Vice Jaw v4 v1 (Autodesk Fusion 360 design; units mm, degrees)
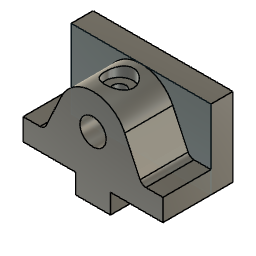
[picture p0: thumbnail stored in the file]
sketch "Sketch1" plane through (0, 0, 0) normal (0, 0, 1) x axis (1, 0, 0)
  line L1 (-32, 5) -> (32, 5)
  line L2 (-32, -5) -> (-32, 5)
  line L3 (32, -5) -> (-32, -5)
  line L4 (32, 5) -> (32, -5)
  line L5 (-32, -5) -> (32, 5)
  line L6 (32, -5) -> (-32, 5)
  point P6 (0, 0)
  point P1 (0, 0)
  point P4 (-32, -5)
  point P5 (32, -5)
  point P3 (-32, 5)
  horizontal L1
  perpendicular L1 L2
  parallel L1 L3
  parallel L2 L4
  coincident L5 P6
  coincident L6 P6
  coincident P1 P6
  dimension "d1" distance P4 P5 = 64
  dimension "d2" distance P3 P4 = 10
extrude "Extrude1" new body sketch "Sketch1" profile of L1 L2 L3 L4 along normal blind 36
sketch "Sketch2" plane through (0, -5, 0) normal (0, -1, 0) x axis (1, 0, 0)
sketch "Sketch3" plane through (0, -5, 0) normal (0, -1, 0) x axis (1, 0, 0)
  line L1 (32, 0) -> (-32, 0)
  line L2 (32, 36) -> (32, 0)
  line L3 (-32, 36) -> (32, 36)
  line L4 (-32, 0) -> (-32, 36)
sketch "Sketch4" plane through (0, -5, 0) normal (0, -1, 0) x axis (1, 0, 0)
  line L1 (-32, 10) -> (-32, 0)
  line L2 (-24.2283, 10) -> (-32, 10)
  line L3 (21.5094, 11.7321) -> (14.5009, 26.7619)
  line L4 (-32, 36) -> (32, 36)
  line L5 (0, 41.3569) -> (0, 0)
  line L6 (32, 10) -> (32, 0)
  line L7 (24.2283, 10) -> (32, 10)
  line L8 (-8, 0) -> (-32, 0)
  line L9 (-8, -9) -> (-8, 0)
  line L10 (8, -9) -> (-8, -9)
  line L11 (8, 0) -> (8, -9)
  line L12 (32, 0) -> (8, 0)
  line L13 (-14.5009, 26.7619) -> (-21.5094, 11.7321)
  arc A1 centre (-24.2283, 13) radius 3 clockwise from (-21.5094, 11.7321) to (-24.2283, 10)
  arc A2 centre (24.2283, 13) radius 3 clockwise from (24.2283, 10) to (21.5094, 11.7321)
  arc A3 centre (0, 20) radius 16 clockwise from (-14.5009, 26.7619) to (14.5009, 26.7619)
  point P2 (-32, 0)
  point P8 (-32, 0)
  point P1 (0, 0)
  point P11 (0, 0)
  point P13 (32, 0)
  point P18 (32, 0)
  point P23 (0, 20)
  point P14 (32, 10)
  vertical L1
  perpendicular L1 L2
  tangent L2 A1
  coincident P2 P8
  tangent A1 L13
  coincident P1 P11
  perpendicular L4 L5
  parallel L5 L6
  perpendicular L5 L7
  tangent L7 A2
  tangent L3 A2
  coincident P13 P18
  perpendicular L1 L8
  perpendicular L8 L9
  perpendicular L1 L10
  perpendicular L8 L11
  perpendicular L6 L12
  symmetric L5 L9 L11
  symmetric L3 L5 L13
  symmetric L2 L5 L7
  symmetric A1 L5 A2
  coincident L5 P23
  tangent L4 A3
  tangent L3 A3
  tangent L13 A3
  dimension "d12" diameter A3 = 32
  dimension "d13" radius A2 = 3
  dimension "d14" distance P13 P14 = 10
  dimension "d15" angle L5 L13 = 25
  dimension "d16" distance L8 L10 = 9
  dimension "d17" distance P1 L9 = 8
extrude "Extrude2" add sketch "Sketch4" profile of L1 L2 A1 L13 L3 L6 L7 A2 L8 L9 L10 L11 L12 A3 along normal blind 22
sketch "Sketch5" plane through (0, -27, 0) normal (0, -1, 0) x axis (1, 0, 0)
  line L1 (14.5009, 26.7619) -> (21.5094, 11.7321)
  line L2 (-21.5094, 11.7321) -> (-14.5009, 26.7619)
  line L3 (-32, 10) -> (-24.2283, 10)
  line L4 (-32, 0) -> (-32, 10)
  line L5 (-8, 0) -> (-32, 0)
  line L6 (-8, -9) -> (-8, 0)
  line L7 (8, -9) -> (-8, -9)
  line L8 (8, 0) -> (8, -9)
  line L9 (32, 0) -> (8, 0)
  line L10 (32, 10) -> (32, 0)
  line L11 (24.2283, 10) -> (32, 10)
  arc A1 centre (0, 20) radius 16 clockwise from (-14.5009, 26.7619) to (14.5009, 26.7619)
  arc A2 centre (-24.2283, 13) radius 3 clockwise from (-21.5094, 11.7321) to (-24.2283, 10)
  arc A3 centre (24.2283, 13) radius 3 clockwise from (24.2283, 10) to (21.5094, 11.7321)
  circle C1 centre (0, 20) radius 6
  concentric A1 C1
  dimension "d20" diameter C1 = 12
extrude "Extrude3" cut sketch "Sketch5" profile of C1 against normal blind 24
sketch "Sketch6" plane through (0, 0, -9) normal (0, 0, -1) x axis (1, 0, 0)
extrude "Extrude4" add of existing geometry blind 10
sketch "Sketch7" plane through (0, 0, -9) normal (0, 0, -1) x axis (1, 0, 0)
  line L1 (8, 27) -> (8, -5)
  line L2 (-8, 27) -> (8, 27)
  line L3 (-8, -5) -> (-8, 27)
  line L4 (8, -5) -> (-8, -5)
  line L5 (0, 31.8303) -> (0, -20.2053)
  point P1 (0, 0)
  point P8 (0, 19)
  point P9 (0, 3)
  perpendicular L2 L5
  coincident P1 L5
  coincident L5 P8
  coincident L5 P9
  dimension "d27" distance P8 P9 = 16
  dimension "d28" distance L2 P8 = 8
hole "Hole1" HoleDepth 16 HoleDiameter 6 TipAngle 118
sketch "Sketch8" plane through (0, 0, 36) normal (0, 0, 1) x axis (-1, 0, 0)
  line L1 (-32, -5) -> (-32, 5)
  line L2 (32, -5) -> (-32, -5)
  line L3 (32, 5) -> (32, -5)
  line L4 (0, 5) -> (32, 5)
  line L5 (-32, 5) -> (0, 5)
  line L6 (0, 23.2468) -> (0, 0)
  point P1 (0, 0)
  point P8 (0, 0)
  point P7 (0, 15)
  coincident P1 P8
  vertical L6
  coincident P7 L6
  dimension "d32" distance L2 P7 = 20
hole "Hole2" HoleDepth 16 HoleDiameter 6 TipAngle 120 CBDepth 5 CBDiameter 13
